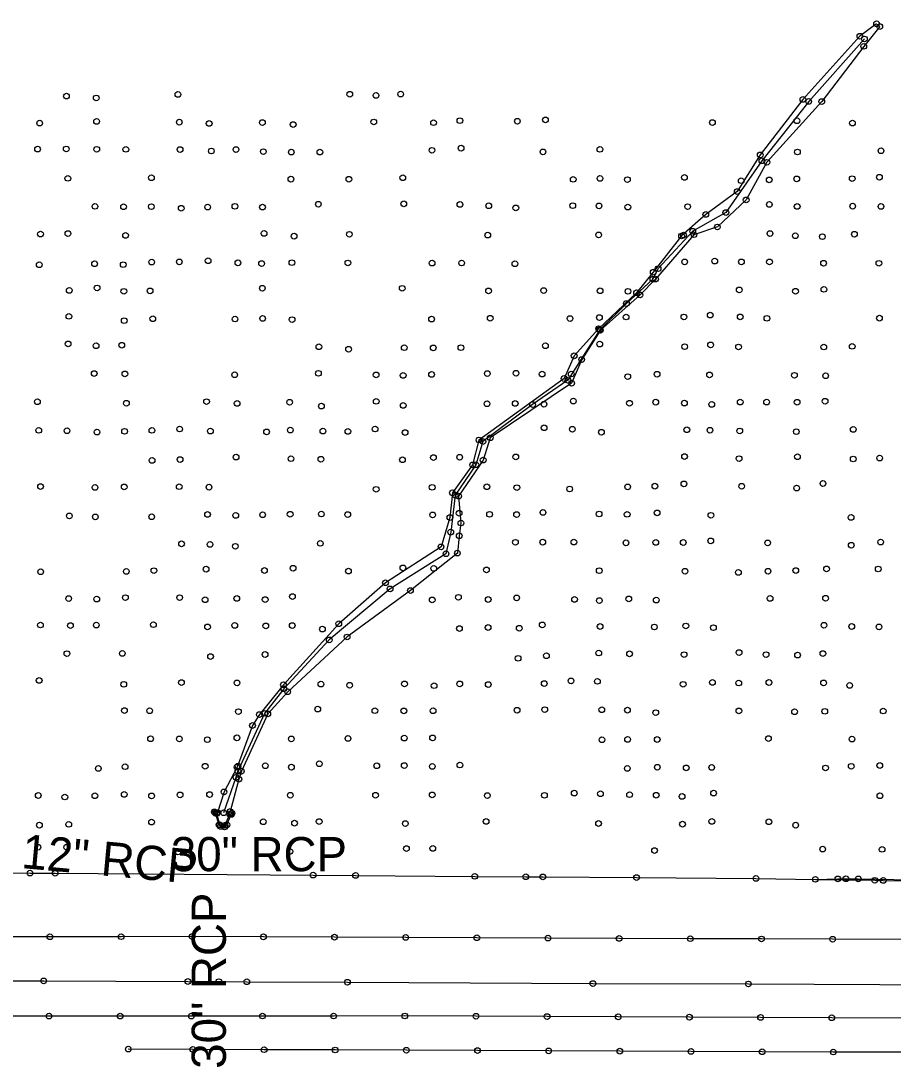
# Model space of a CAD drawing. Extents: x 20503438 to 20508873, y 7964251 to 7984667.
# Drawn here: x 20507655.5 to 20507961.9, y 7970510.6 to 7970878 of the extents above; entities that cross this region are included whole.
import ezdxf

# ---------------------------------------------------------------- set-up
doc = ezdxf.new("R2010")
doc.units = 0
for name, color, linetype in [('SurBreakLine', 7, 'Continuous'), ('SurConcreteSlab', 7, 'Continuous'), ('SurDrainageArrowUp', 7, 'Continuous'), ('SurEdgeCurb', 7, 'Continuous'), ('SurEdgeRoadPaved', 7, 'Continuous'), ('SurPointsNonDTM', 7, 'Continuous'), ('SurSurveyPoints', 7, 'Continuous'), ('SurTxtDrainage', 7, 'Continuous')]:
    doc.layers.add(name, color=color, linetype=linetype)

msp = doc.modelspace()

# ---------------------------------------------------------------- linework, layer by layer
at = {"layer": 'SurBreakLine'}
for points in [[(20507956.13, 7970877), (20507950.27, 7970872.61), (20507930.22, 7970850.44), (20507915.24, 7970830.93), (20507907.15, 7970818.05), (20507896.12, 7970810.02), (20507887.6, 7970802.46), (20507877.64, 7970789.75), (20507871.8, 7970782.51), (20507858.47, 7970769.91), (20507849.87, 7970760.37), (20507846.32, 7970752.41), (20507816.43, 7970730.81), (20507814.2, 7970722.06), (20507807.08, 7970712.27), (20507806.23, 7970703.58), (20507803.09, 7970693.28), (20507783.59, 7970680.65), (20507767.18, 7970666.28), (20507747.72, 7970644.84), (20507739.29, 7970634.36), (20507736.86, 7970630.54), (20507731.43, 7970615.86), (20507726.85, 7970607.2), (20507724.58, 7970599.95), (20507723.47, 7970600.21)], [(20507957.24, 7970876.01), (20507951.6, 7970869.06), (20507936.86, 7970849.67), (20507917.6, 7970828.34), (20507910.3, 7970815.14), (20507900.18, 7970805.63), (20507891.96, 7970802.92), (20507878.46, 7970787.32), (20507873.01, 7970781.76), (20507859.07, 7970769.36), (20507852.52, 7970759.07), (20507848.99, 7970750.77), (20507820.39, 7970731.6), (20507817.9, 7970723.75), (20507809.29, 7970711.11), (20507810.09, 7970701.65), (20507809.51, 7970697.16), (20507808.83, 7970691.07), (20507792.36, 7970677.94), (20507770.11, 7970661.63), (20507749.22, 7970642.39), (20507742.21, 7970634.62), (20507732.94, 7970614.5), (20507732.08, 7970611.68), (20507729.03, 7970600.35), (20507729.6, 7970599.76)], [(20507723.47, 7970600.21), (20507723.7, 7970599.81), (20507725.08, 7970595.67), (20507725.63, 7970595.09), (20507727.01, 7970594.88), (20507727.89, 7970595.68), (20507729.39, 7970599.29), (20507729.6, 7970599.76)], [(20507578.75, 7970541.01), (20507620.38, 7970540.8), (20507663.5, 7970540.83), (20507714.16, 7970540.62), (20507734.86, 7970540.54), (20507770.2, 7970540.37), (20507856.47, 7970539.89), (20507911.07, 7970539.76), (20508003.36, 7970539.32), (20508047.5, 7970539.58), (20508093.59, 7970539.01), (20508125.03, 7970538.88), (20508139.33, 7970538.81), (20508184.85, 7970538.49)]]:
    msp.add_lwpolyline(points, dxfattribs=at)
at = {"layer": 'SurConcreteSlab'}
for points in [[(20507724.23, 7970599.57), (20507725.37, 7970595.67), (20507727.19, 7970595.47), (20507728.88, 7970599.44)], [(20508167.82, 7970554.19), (20508144.63, 7970554.39), (20508119.63, 7970554.61), (20508094.64, 7970554.82), (20508069.64, 7970555.04), (20508040.67, 7970555.17), (20508015.67, 7970555.21), (20507990.67, 7970555.24), (20507965.68, 7970555.34), (20507940.68, 7970555.45), (20507915.68, 7970555.56), (20507890.68, 7970555.66), (20507865.68, 7970555.77), (20507840.68, 7970555.88), (20507815.68, 7970555.99), (20507790.68, 7970556.09), (20507765.69, 7970556.2), (20507740.69, 7970556.31), (20507715.69, 7970556.39), (20507690.69, 7970556.36), (20507665.7, 7970556.34), (20507640.7, 7970556.31)], [(20508159, 7970527.1), (20508147.96, 7970527.15), (20508122.96, 7970527.28), (20508097.97, 7970527.4), (20508072.97, 7970527.52), (20508040.35, 7970527.64), (20508015.35, 7970527.67), (20507990.36, 7970527.71), (20507965.36, 7970527.79), (20507940.36, 7970527.89), (20507915.36, 7970528), (20507890.36, 7970528.1), (20507865.36, 7970528.21), (20507840.36, 7970528.31), (20507815.37, 7970528.42), (20507790.37, 7970528.51), (20507765.37, 7970528.5), (20507740.37, 7970528.5), (20507715.37, 7970528.49), (20507690.37, 7970528.49), (20507665.37, 7970528.48), (20507640.37, 7970528.48)], [(20508169.07, 7970514.98), (20508148.11, 7970514.92), (20508123.11, 7970514.84), (20508098.12, 7970514.76), (20508073.12, 7970514.68), (20508040.9, 7970514.94), (20508015.91, 7970515.31), (20507990.91, 7970515.65), (20507965.91, 7970515.75), (20507940.91, 7970515.85), (20507915.92, 7970515.96), (20507890.92, 7970516.06), (20507865.92, 7970516.16), (20507840.92, 7970516.26), (20507815.92, 7970516.37), (20507790.92, 7970516.47), (20507765.92, 7970516.57), (20507740.92, 7970516.67), (20507715.93, 7970516.77), (20507693.23, 7970516.87)]]:
    msp.add_lwpolyline(points, dxfattribs=at)
at = {"layer": 'SurDrainageArrowUp'}
msp.add_lwpolyline([(20507951.83, 7970871.66), (20507932.26, 7970849.71), (20507915.82, 7970828.88), (20507903.16, 7970810.7), (20507891.52, 7970804.13), (20507879.35, 7970790.99), (20507877.53, 7970787.33), (20507868.23, 7970778.74), (20507858.87, 7970769.56), (20507847.7, 7970751.77), (20507835.26, 7970743.25), (20507817.78, 7970730.25), (20507815.34, 7970722.12), (20507808.12, 7970711.45), (20507806.5, 7970698.48), (20507804.84, 7970690.84), (20507785.19, 7970678.53), (20507763.82, 7970660.6), (20507747.88, 7970643.42), (20507741.08, 7970634.8), (20507731.72, 7970614.52), (20507731.06, 7970612.33), (20507726.73, 7970599.87)], dxfattribs=at)
at = {"layer": 'SurEdgeCurb'}
msp.add_lwpolyline([(20507934.6, 7970576.5), (20507942.51, 7970576.67), (20507945.34, 7970576.7), (20507949.7, 7970576.64), (20507974.69, 7970576.22), (20507998.31, 7970576.09), (20508000.94, 7970576.22)], dxfattribs=at)
at = {"layer": 'SurEdgeRoadPaved'}
msp.add_lwpolyline([(20507614.92, 7970579.02), (20507658.7, 7970578.69), (20507667.54, 7970578.63), (20507758.14, 7970578), (20507773.09, 7970577.88), (20507814.95, 7970577.55), (20507832.88, 7970577.41), (20507838.86, 7970577.36), (20507871.78, 7970577.11), (20507913.74, 7970576.83), (20507934.61, 7970576.5), (20507955.48, 7970576.17), (20507958.47, 7970576.12), (20507998.3, 7970575.54), (20508004.64, 7970575.98)], dxfattribs=at)
at = {"layer": 'SurPointsNonDTM'}
msp.add_circle((20507725, 7970540.58), 1, dxfattribs=at)
at = {"layer": 'SurSurveyPoints'}
for centre in [(20507956.13, 7970877), (20507957.24, 7970876.01), (20507950.27, 7970872.61), (20507951.83, 7970871.66), (20507951.6, 7970869.06), (20507671.5, 7970851.59), (20507681.97, 7970850.94), (20507710.66, 7970852.19), (20507771.04, 7970852.24), (20507780.26, 7970851.83), (20507788.92, 7970852.31), (20507930.22, 7970850.44), (20507932.26, 7970849.71), (20507936.86, 7970849.67), (20507662.09, 7970842.1), (20507682.09, 7970842.71), (20507711.15, 7970842.44), (20507721.64, 7970841.99), (20507740.34, 7970842.3), (20507779.48, 7970842.51), (20507800.46, 7970842.26), (20507809.71, 7970842.97), (20507829.91, 7970842.78), (20507839.79, 7970843.24), (20507898.43, 7970842.31), (20507928.14, 7970842.93), (20507947.65, 7970842.12), (20507751.15, 7970841.61), (20507661.36, 7970832.97), (20507671.43, 7970833.03), (20507682.13, 7970832.91), (20507692.36, 7970832.89), (20507711.42, 7970832.83), (20507722.4, 7970832.31), (20507731.06, 7970832.82), (20507740.67, 7970832.09), (20507750.49, 7970831.91), (20507760.53, 7970831.94), (20507799.91, 7970832.56), (20507810.14, 7970833.31), (20507838.91, 7970832.01), (20507858.93, 7970832.89), (20507915.24, 7970830.93), (20507928.32, 7970831.96), (20507957.67, 7970832.39), (20507915.82, 7970828.88), (20507917.6, 7970828.34), (20507671.98, 7970822.7), (20507701.35, 7970822.91), (20507750.37, 7970822.42), (20507770.72, 7970822.38), (20507789.67, 7970822.92), (20507849.53, 7970822.35), (20507858.94, 7970822.69), (20507868.58, 7970822.26), (20507888.62, 7970823.04), (20507908.56, 7970821.88), (20507918.39, 7970822.18), (20507928.06, 7970822.53), (20507947.55, 7970822.61), (20507957.11, 7970823.11), (20507907.15, 7970818.05), (20507681.52, 7970812.87), (20507691.56, 7970812.74), (20507701.32, 7970812.76), (20507721.11, 7970812.63), (20507730.68, 7970812.88), (20507740.37, 7970812.6), (20507760, 7970813.63), (20507790.02, 7970813.76), (20507809.74, 7970813.54), (20507819.87, 7970813.06), (20507829.38, 7970812.33), (20507849.38, 7970813.11), (20507858.61, 7970813.05), (20507868.73, 7970812.61), (20507889.74, 7970812.77), (20507910.3, 7970815.14), (20507918.45, 7970813.54), (20507928.22, 7970812.84), (20507947.73, 7970812.94), (20507957.66, 7970812.83), (20507711.82, 7970812.2), (20507896.12, 7970810.02), (20507903.16, 7970810.7), (20507900.18, 7970805.63), (20507662.38, 7970803.13), (20507672.01, 7970803.31), (20507692.26, 7970802.67), (20507740.93, 7970803.38), (20507751.46, 7970802.4), (20507770.89, 7970803.05), (20507819.5, 7970802.77), (20507858.47, 7970802.84), (20507887.6, 7970802.46), (20507888.28, 7970802.76), (20507891.52, 7970804.13), (20507891.96, 7970802.92), (20507918.67, 7970803.33), (20507927.56, 7970802.55), (20507937.06, 7970802.23), (20507948.33, 7970803.09), (20507661.94, 7970792.37), (20507681.39, 7970792.69), (20507691.43, 7970792.39), (20507701.45, 7970793.31), (20507711.15, 7970793.38), (20507721.28, 7970793.77), (20507731.73, 7970793.04), (20507740.05, 7970792.77), (20507750.69, 7970793.09), (20507770.37, 7970792.99), (20507799.94, 7970792.96), (20507810.34, 7970792.97), (20507829.05, 7970792.71), (20507879.35, 7970790.99), (20507888.69, 7970793.37), (20507899.26, 7970793.66), (20507908.62, 7970793.37), (20507918.5, 7970793.36), (20507937.49, 7970792.9), (20507956.92, 7970792.87), (20507877.53, 7970787.33), (20507877.64, 7970789.75), (20507878.46, 7970787.32), (20507672.48, 7970783.36), (20507682.25, 7970784.21), (20507691.66, 7970783.04), (20507700.88, 7970783.19), (20507740.33, 7970784.12), (20507789.46, 7970784.09), (20507819.79, 7970783.16), (20507839.16, 7970783.29), (20507858.99, 7970783.21), (20507868.77, 7970783.03), (20507907.88, 7970783.51), (20507927.63, 7970783.05), (20507937.61, 7970783.72), (20507871.8, 7970782.51), (20507873.01, 7970781.76), (20507868.23, 7970778.74), (20507672.35, 7970774.23), (20507691.78, 7970772.72), (20507701.83, 7970773.4), (20507730.72, 7970773.3), (20507740.42, 7970773.49), (20507750.76, 7970773.08), (20507799.78, 7970773.26), (20507820.37, 7970773.57), (20507848.42, 7970773.45), (20507858.75, 7970773.82), (20507868.13, 7970774), (20507888.43, 7970774.02), (20507897.67, 7970774.66), (20507908.21, 7970774.05), (20507917.57, 7970773.54), (20507957.13, 7970773.6), (20507858.47, 7970769.91), (20507858.87, 7970769.56), (20507859.07, 7970769.36), (20507672.08, 7970764.56), (20507858.86, 7970764.49), (20507681.9, 7970763.92), (20507690.94, 7970764.11), (20507760.18, 7970763.56), (20507770.62, 7970762.69), (20507790.17, 7970763.23), (20507800.36, 7970763.17), (20507810.09, 7970763.24), (20507839.77, 7970763.92), (20507888.69, 7970763.59), (20507897.81, 7970764.2), (20507907.62, 7970763.48), (20507937.58, 7970763.46), (20507947.55, 7970763.7), (20507849.87, 7970760.37), (20507852.52, 7970759.07), (20507681.24, 7970754.16), (20507692.02, 7970754.02), (20507730.6, 7970753.71), (20507760.01, 7970754.23), (20507780.3, 7970753.67), (20507789.79, 7970753.49), (20507799.77, 7970753.83), (20507819.35, 7970754.14), (20507829.45, 7970754.26), (20507838.61, 7970753.96), (20507848.86, 7970753.98), (20507878.99, 7970753.92), (20507897.43, 7970753.66), (20507927.24, 7970753.53), (20507846.32, 7970752.41), (20507847.7, 7970751.77), (20507848.99, 7970750.77), (20507868.69, 7970753.06), (20507938.22, 7970753.36), (20507661.29, 7970744.24), (20507692.56, 7970743.72), (20507720.72, 7970744.28), (20507731.46, 7970743.67), (20507749.91, 7970744.07), (20507761.06, 7970742.71), (20507780.32, 7970744.38), (20507789.81, 7970742.97), (20507819.25, 7970743.55), (20507829.15, 7970743.65), (20507835.26, 7970743.25), (20507839.27, 7970743.39), (20507849.58, 7970744.48), (20507869.31, 7970743.72), (20507878.52, 7970744.1), (20507888.6, 7970743.76), (20507898.21, 7970743.31), (20507908.2, 7970744.13), (20507917.47, 7970744.12), (20507928.21, 7970744.07), (20507938.02, 7970744.41), (20507839.32, 7970735.1), (20507661.77, 7970734.2), (20507671.69, 7970734.07), (20507682.22, 7970733.6), (20507691.93, 7970733.85), (20507701.52, 7970734.2), (20507711.27, 7970734.66), (20507722.07, 7970733.95), (20507741.81, 7970733.67), (20507750.15, 7970734.29), (20507761.61, 7970733.95), (20507770.36, 7970733.83), (20507779.92, 7970734.66), (20507790.48, 7970733.44), (20507820.39, 7970731.6), (20507849.23, 7970734.58), (20507859.44, 7970733.55), (20507889.45, 7970734.4), (20507897.58, 7970734.25), (20507908.05, 7970733.98), (20507927.91, 7970733.74), (20507947.93, 7970734.53), (20507816.43, 7970730.81), (20507817.78, 7970730.25), (20507731.09, 7970724.79), (20507750.38, 7970724.24), (20507760.9, 7970724.05), (20507800.44, 7970724.63), (20507809.64, 7970724.77), (20507829.36, 7970724.86), (20507888.65, 7970725), (20507907.8, 7970724.26), (20507928.32, 7970724.94), (20507947.91, 7970724.14), (20507957.19, 7970724.47), (20507701.58, 7970723.65), (20507711.42, 7970723.95), (20507789.55, 7970723.85), (20507814.2, 7970722.06), (20507815.34, 7970722.12), (20507817.9, 7970723.75), (20507662.39, 7970714.47), (20507681.54, 7970714.16), (20507691.79, 7970714.32), (20507711.11, 7970714.41), (20507721.58, 7970714.24), (20507780.31, 7970713.49), (20507799.98, 7970714.19), (20507819.19, 7970714.38), (20507829.73, 7970714.08), (20507848.29, 7970713.6), (20507868.67, 7970714.35), (20507878.22, 7970714.6), (20507888.43, 7970715.4), (20507908.73, 7970714.56), (20507928.04, 7970713.92), (20507937.28, 7970715.53), (20507807.08, 7970712.27), (20507808.12, 7970711.45), (20507809.29, 7970711.11), (20507672.51, 7970704.14), (20507681.64, 7970703.82), (20507701.45, 7970703.84), (20507721.06, 7970704.65), (20507730.98, 7970704.32), (20507740.42, 7970704.54), (20507750.09, 7970704.74), (20507761.05, 7970704.81), (20507770.33, 7970704.61), (20507800.15, 7970704.49), (20507806.23, 7970703.58), (20507809.45, 7970705.07), (20507820.16, 7970704.7), (20507829.65, 7970704.62), (20507838.92, 7970705.36), (20507858.64, 7970704.82), (20507868.49, 7970704.69), (20507879.02, 7970705.22), (20507897.92, 7970704.36), (20507947.16, 7970703.62), (20507806.5, 7970698.48), (20507810.09, 7970701.65), (20507809.51, 7970697.16), (20507829.23, 7970694.88), (20507838.84, 7970694.93), (20507849.76, 7970694.96), (20507868.07, 7970694.69), (20507878.55, 7970694.84), (20507888.2, 7970694.81), (20507897.85, 7970695.38), (20507917.86, 7970694.67), (20507957.54, 7970694.96), (20507711.93, 7970694.34), (20507721.94, 7970694.13), (20507730.83, 7970693.47), (20507760.69, 7970694.51), (20507803.09, 7970693.28), (20507808.83, 7970691.07), (20507947.21, 7970693.86), (20507804.84, 7970690.84), (20507662.44, 7970684.52), (20507692.52, 7970684.65), (20507702.21, 7970684.93), (20507720.55, 7970685.44), (20507741.06, 7970684.98), (20507751.12, 7970685.78), (20507770.58, 7970684.76), (20507789.7, 7970685.9), (20507800.53, 7970685.72), (20507819.06, 7970685.17), (20507858.68, 7970684.92), (20507888.82, 7970684.7), (20507907.58, 7970684.31), (20507917.98, 7970684.73), (20507927.73, 7970684.96), (20507938.53, 7970685.54), (20507956.69, 7970685.5), (20507783.59, 7970680.65), (20507785.19, 7970678.53), (20507792.36, 7970677.94), (20507672.29, 7970675.11), (20507682.15, 7970674.95), (20507692.22, 7970675.44), (20507711.27, 7970675.44), (20507720.22, 7970674.7), (20507731.35, 7970675.15), (20507741.31, 7970674.75), (20507750.9, 7970675.82), (20507800, 7970674.65), (20507809.2, 7970675.56), (20507819.67, 7970674.79), (20507829.68, 7970675.37), (20507850, 7970674.82), (20507858.72, 7970674.4), (20507869.07, 7970674.99), (20507878.72, 7970674.58), (20507918.69, 7970675.18), (20507938.2, 7970675.22), (20507662.36, 7970665.83), (20507672.91, 7970665.62), (20507681.99, 7970665.8), (20507702.04, 7970665.94), (20507730.63, 7970665.68), (20507741.54, 7970665.51), (20507750.83, 7970665.65), (20507767.18, 7970666.28), (20507838.65, 7970665.87), (20507859, 7970665.31), (20507889.1, 7970665.49), (20507937.63, 7970665.74), (20507947.38, 7970665.31), (20507721.07, 7970665.17), (20507761.42, 7970664.38), (20507770.11, 7970661.63), (20507809.58, 7970664.6), (20507819.64, 7970664.96), (20507830.58, 7970664.7), (20507878.05, 7970665.13), (20507898.79, 7970664.9), (20507956.97, 7970665.15), (20507763.82, 7970660.6), (20507671.66, 7970655.78), (20507691.12, 7970655.86), (20507722.11, 7970654.76), (20507741.27, 7970655.47), (20507840.12, 7970655.04), (20507858.51, 7970655.99), (20507869.32, 7970655.71), (20507888.51, 7970655.42), (20507907.8, 7970656.15), (20507917.3, 7970655.42), (20507928.36, 7970655.25), (20507937.25, 7970655.8), (20507830.18, 7970654.13), (20507661.91, 7970646.35), (20507691.62, 7970645), (20507711.91, 7970645.6), (20507731.42, 7970645.49), (20507747.72, 7970644.84), (20507747.88, 7970643.42), (20507760.89, 7970645.09), (20507770.99, 7970644.66), (20507790.26, 7970645.13), (20507800.68, 7970644.52), (20507809.66, 7970645.14), (20507819.7, 7970644.93), (20507839.36, 7970645.27), (20507848.76, 7970646.19), (20507858.04, 7970646.04), (20507888.17, 7970645.01), (20507898.46, 7970645.67), (20507907.7, 7970645.45), (20507918.29, 7970645.64), (20507937.5, 7970645.5), (20507946.67, 7970644.61), (20507749.22, 7970642.39), (20507759.78, 7970636.29), (20507829.82, 7970635.91), (20507839.54, 7970636.11), (20507859.58, 7970636.07), (20507868.59, 7970635.92), (20507691.88, 7970635.78), (20507700.72, 7970635.73), (20507731.9, 7970635.41), (20507739.29, 7970634.36), (20507741.08, 7970634.8), (20507742.21, 7970634.62), (20507779.85, 7970635.74), (20507790.03, 7970635.68), (20507800.31, 7970635.72), (20507878.53, 7970635.05), (20507907.74, 7970635.66), (20507927.31, 7970635.36), (20507937.92, 7970635.51), (20507958.45, 7970635.62), (20507736.86, 7970630.54), (20507701.05, 7970625.86), (20507711.17, 7970625.83), (20507720.98, 7970625.56), (20507731.39, 7970626.21), (20507750.49, 7970625.82), (20507770.41, 7970625.98), (20507790.17, 7970626.11), (20507800.14, 7970626.2), (20507859.64, 7970625.53), (20507868.63, 7970625.66), (20507879.05, 7970625.62), (20507918.13, 7970625.93), (20507947.47, 7970625.78), (20507682.7, 7970615.45), (20507692.09, 7970616.07), (20507720.23, 7970616.23), (20507731.43, 7970615.86), (20507731.72, 7970614.52), (20507731.77, 7970616.28), (20507732.94, 7970614.5), (20507741.36, 7970616.4), (20507750.52, 7970615.9), (20507760.34, 7970617.1), (20507780.51, 7970616.38), (20507790.17, 7970616.46), (20507800.03, 7970616.17), (20507809.74, 7970616.65), (20507868.54, 7970615.47), (20507879.08, 7970615.89), (20507889.23, 7970615.66), (20507898.19, 7970615.8), (20507938.19, 7970615.62), (20507947.22, 7970616.21), (20507957.25, 7970616.49), (20507731.06, 7970612.33), (20507732.08, 7970611.68), (20507726.85, 7970607.2), (20507849.91, 7970606.78), (20507859.11, 7970606.57), (20507898.86, 7970606.79), (20507661.6, 7970605.95), (20507670.93, 7970605.42), (20507681.48, 7970605.87), (20507691.78, 7970606.33), (20507701.42, 7970605.81), (20507711.42, 7970606.16), (20507721.78, 7970606.29), (20507750.14, 7970606.04), (20507780.09, 7970606.04), (20507800, 7970606.15), (20507819.37, 7970605.91), (20507839.43, 7970606.01), (20507869.35, 7970606.23), (20507878.7, 7970606.06), (20507887.78, 7970605.61), (20507957.3, 7970605.85), (20507723.47, 7970600.21), (20507723.7, 7970599.81), (20507724.23, 7970599.57), (20507724.58, 7970599.95), (20507726.73, 7970599.87), (20507728.88, 7970599.44), (20507729.03, 7970600.35), (20507729.39, 7970599.29), (20507729.6, 7970599.76), (20507661.99, 7970595.53), (20507672.31, 7970595.81), (20507701.39, 7970596.62), (20507725.08, 7970595.67), (20507725.37, 7970595.67), (20507727.19, 7970595.47), (20507727.89, 7970595.68), (20507740.63, 7970596.74), (20507751.63, 7970596.23), (20507760.28, 7970596.78), (20507790.56, 7970596.08), (20507818.94, 7970596.83), (20507858.43, 7970596.12), (20507887.93, 7970595.88), (20507898.24, 7970596.86), (20507918.27, 7970596.71), (20507927.69, 7970595.53), (20507725.63, 7970595.09), (20507727.01, 7970594.88), (20507661.48, 7970587.79), (20507671.57, 7970587.78), (20507710.65, 7970586.14), (20507749.99, 7970586.31), (20507790.96, 7970587.31), (20507800.21, 7970587.38), (20507878.1, 7970586.62), (20507937.19, 7970587.12), (20507958.06, 7970587.03), (20507658.7, 7970578.69), (20507667.54, 7970578.63), (20507758.14, 7970578), (20507773.09, 7970577.88), (20507814.95, 7970577.55), (20507832.88, 7970577.41), (20507838.86, 7970577.36), (20507871.78, 7970577.11), (20507913.74, 7970576.83), (20507934.6, 7970576.5), (20507934.61, 7970576.5), (20507942.51, 7970576.67), (20507945.34, 7970576.7), (20507949.7, 7970576.64), (20507955.48, 7970576.17), (20507958.47, 7970576.12), (20507665.7, 7970556.34), (20507690.69, 7970556.36), (20507715.69, 7970556.39), (20507740.69, 7970556.31), (20507765.69, 7970556.2), (20507790.68, 7970556.09), (20507815.68, 7970555.99), (20507840.68, 7970555.88), (20507865.68, 7970555.77), (20507890.68, 7970555.66), (20507915.68, 7970555.56), (20507940.68, 7970555.45), (20507663.5, 7970540.83), (20507714.16, 7970540.62), (20507734.86, 7970540.54), (20507770.2, 7970540.37), (20507856.47, 7970539.89), (20507911.07, 7970539.76), (20507665.37, 7970528.48), (20507690.37, 7970528.49), (20507715.37, 7970528.49), (20507740.37, 7970528.5), (20507765.37, 7970528.5), (20507790.37, 7970528.51), (20507815.37, 7970528.42), (20507840.36, 7970528.31), (20507865.36, 7970528.21), (20507890.36, 7970528.1), (20507915.36, 7970528), (20507940.36, 7970527.89), (20507693.23, 7970516.87), (20507715.93, 7970516.77), (20507740.92, 7970516.67), (20507765.92, 7970516.57), (20507790.92, 7970516.47), (20507815.92, 7970516.37), (20507840.92, 7970516.26), (20507865.92, 7970516.16), (20507890.92, 7970516.06), (20507915.92, 7970515.96), (20507940.91, 7970515.85)]:
    msp.add_circle(centre, 1, dxfattribs=at)

# ---------------------------------------------------------------- texts
at = {"layer": 'SurTxtDrainage'}
for s, rotation, p in [('12" RCP', 354.7654, (20507655.41, 7970580.49)), ('30" RCP', 90, (20507727.51, 7970509.96))]:
    msp.add_text(s, height=12, rotation=rotation, dxfattribs=at).set_placement(p)
msp.add_text('30" RCP', height=12, dxfattribs=at).set_placement((20507708.17, 7970579.36))

doc.saveas('drawing.dxf')
